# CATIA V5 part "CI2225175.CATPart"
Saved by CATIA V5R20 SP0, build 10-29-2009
Part number: CI2225175
Bounding box of the stored display mesh (mm): x -24 to 24, y -18.534 to 209.5, z -34.099 to 26.514
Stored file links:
  C:\Users\Raffaele\Desktop\3D X SITO CF\BOLEX\19-INCLINED ASSEMBLY REF_CI\CI2225175.CATPart
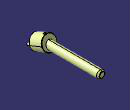
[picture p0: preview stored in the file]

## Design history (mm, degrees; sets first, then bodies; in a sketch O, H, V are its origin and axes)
Set1
  DatumSurface1 to DatumSurface16 "MANIFOLD_SOLID_BREP #393"
  DatumSurface17 to DatumSurface39 "MANIFOLD_SOLID_BREP #1138"
Body1 (main body)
